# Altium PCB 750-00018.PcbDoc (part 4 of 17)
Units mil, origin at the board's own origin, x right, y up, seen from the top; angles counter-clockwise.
Board outline 7086.64 x 6299.21 mil, 8 copper layers (Top Layer, L2, L3, L4, L5, L6, L7, Bottom Layer), stack 60.6 mil thick; 1356 components, 1054 nets, 4851 pads, 4296 vias.
Unrouted connection lines stored in the file: 12.
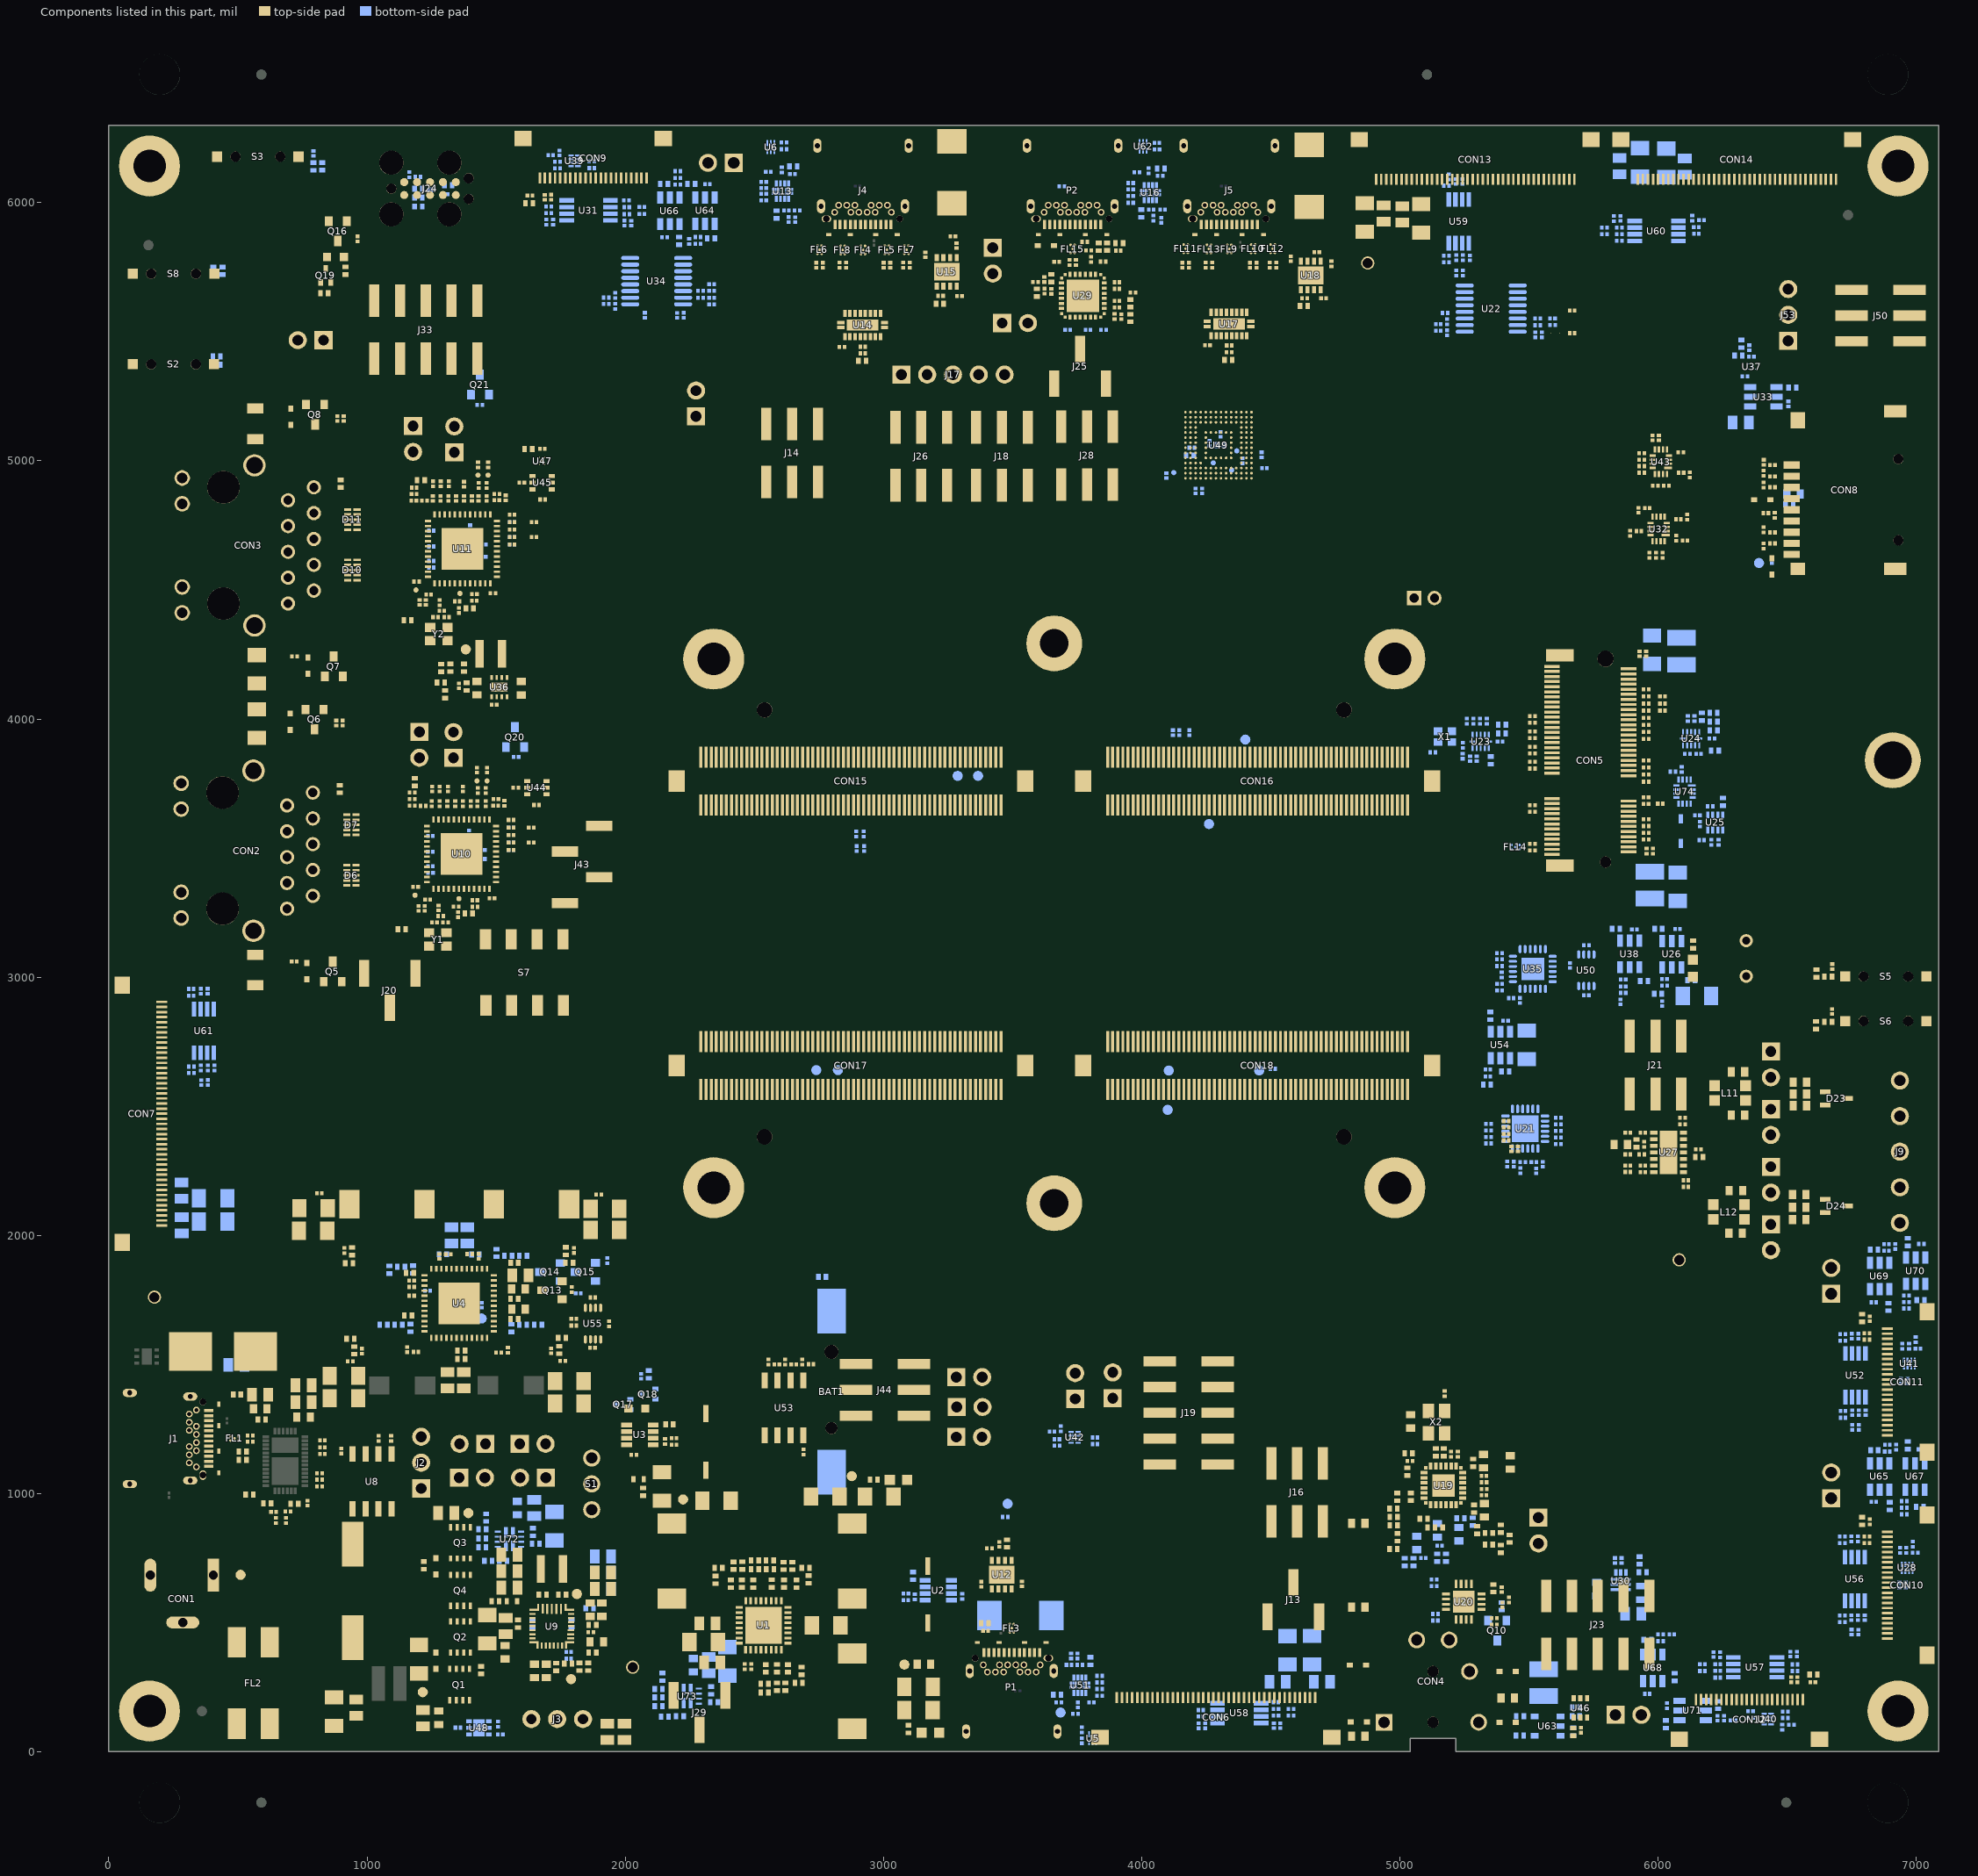
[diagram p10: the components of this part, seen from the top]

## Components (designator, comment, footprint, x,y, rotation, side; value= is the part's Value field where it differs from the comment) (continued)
U9 "TI, BQ25792RQM#" "VQFN29, 4x4, Pitch 0.45 & 0.4mm, Height 1mm" 1715.57,486.56 r0 top value=BQ25792RQM#
U10 "TI, DP83867IRRGZ" "QFN48, 7x7, Pitch 0.5mm, Height 1.0mm" 1365.54,3476.67 r0 top value=DP83867IRRGZ
U11 "TI, DP83867IRRGZ" "QFN48, 7x7, Pitch 0.5mm, Height 1.0mm" 1369.48,4658.99 r0 top value=DP83867IRRGZ
U12 "TI, TPS2557DRBT" "VSON8, 3mm x 3mm, Height 1.0mm, SMD" 3458.2,686 r270 top value=TPS2557DRBT
U13 "TI, TUSB321RWBR" "X2QFN12, 1.6mm x 1.6mm, Pitch 0.4mm, Height 0.4mm, SMD" 2608.95,6043.99 r180 bottom value=TUSB321RWBR
U14 "TI, HD3SS3212IRKST" "VQFN20, 2.5x4.5, Pitch 0.5mm, Height 1.0mm, SMD" 2919.66,5525.87 r90 top value=HD3SS3212IRKST
U15 "TI, TPS2557DRBT" "VSON8, 3mm x 3mm, Height 1.0mm, SMD" 3244.75,5732.09 r90 top value=TPS2557DRBT
U16 "TI, TUSB321RWBR" "X2QFN12, 1.6mm x 1.6mm, Pitch 0.4mm, Height 0.4mm, SMD" 4033.67,6038.46 r180 bottom value=TUSB321RWBR
U17 "TI, HD3SS3212IRKST" "VQFN20, 2.5x4.5, Pitch 0.5mm, Height 1.0mm, SMD" 4338.14,5529.98 r90 top value=HD3SS3212IRKST
U18 "TI, TPS2557DRBT" "VSON8, 3mm x 3mm, Height 1.0mm, SMD" 4654.57,5718.14 r90 top value=TPS2557DRBT
U19 "TI, TAC5112IRGER" "VQFN24, 4x4, Pitch 0.5mm, Height 1.0mm, SMD with Anchor Pads" 5168.69,1031.74 r180 top value=TAC5112IRGER
U20 "TI, TS3A227ERVAR" "QFN16, 3.5x3.5, Pitch 0.5mm, Height 1.0mm" 5247,581.34 r180 top value=TS3A227ERVAR
U21 "Microchip, MCP23018-E/MJ" "VQFN24, 4x4, Pitch 0.5mm, Height 0.9mm" 5485.26,2413.17 r270 bottom value=MCP23018-E/MJ
U22 "TI, TCA9546APWR" "TSSOP16, 16-Leads, Body 5.0mm x 4.4mm, Height 1.2mm, Pitch 0.65mm" 5353.7,5589.13 r0 bottom value=TCA9546APWR
U23 "TI, LSF0204RUTR" "TI, RUT12" 5312.93,3912.95 r90 bottom value=LSF0204RUTR
U24 "TI, LSF0204RUTR" "TI, RUT12" 6127.81,3924.27 r90 bottom value=LSF0204RUTR
U25 "TI, TPS2116DRLR" "SOT8, 2.1x1.6mm, Height 0.6mm" 6221.4,3599.27 r90 bottom value=TPS2116DRLR
U26 "TI, TPS22918DBVR" "SOT23_6, Height 1.45mm" 6053.01,3089.32 r90 bottom value=TPS22918DBVR
U27 "TI, TCAN1046AVDMTRQ1" "SON14, 4.5mm x 3mm x 1mm, SMD" 6040.4,2320.97 r0 top value=TCAN1046AVDMTRQ1
U28 "TI, LSF0102DQER" "XFDFN8, 1.4x1.0, 0.4mm" 6964.7,712.89 r90 bottom value=LSF0102DQER
U29 "FTDI, FT232RNQ" "QFN32, 5x5, Pitch 0.5mm, Height 0.9mm" 3771.98,5639.24 r180 top value=FT232RNQ
U30 "TI, TPS62902RPJR" "VQFN-HR(9), 1.5mm x 2.0mm, Pitch 0.5mm, Height 1mm, SMD" 5855.43,658.16 r180 bottom value=TPS62902RPJR
U31 "TI, TCA9617BDGKR" "TSSOP8, 4.9x3, Pitch 0.65mm, Height 1.1mm" 1857.97,5969.85 r0 bottom value=TCA9617BDGKR
U32 "TI, TMUX1574RSVR" "UQFN16, 2.6x1.8, Pitch 0.4mm, Height 0.5mm" 6001.69,4735.84 r180 top value=TMUX1574RSVR
U33 "TI, TPS22918DBVR" "SOT23_6, Height 1.45mm" 6407.31,5247.2 r0 bottom value=TPS22918DBVR
U34 "TI, TCA9546APWR" "TSSOP16, 16-Leads, Body 5.0mm x 4.4mm, Height 1.2mm, Pitch 0.65mm" 2121.74,5695.52 r0 bottom value=TCA9546APWR
U35 "TI, TCAL9539RTWR" "QFN24, 4x4, Pitch 0.5mm, Height 0.8mm" 5514.39,3031.87 r270 bottom value=TCAL9539RTWR
U36 "TI, TLV62065DSGR" DSG0008A 1511.91,4123.41 r270 top value=TLV62065DSGR
U37 "TI, SN74LVC1G08DPWR" "TI, SN74LVC1G08DPWR" 6362.83,5365.12 r180 bottom value=SN74LVC1G08DPWR
U38 "TI, TPS22918DBVR" "SOT23_6, Height 1.45mm" 5889.82,3089.76 r90 bottom value=TPS22918DBVR
U39 "TI, LSF0102DQER" "XFDFN8, 1.4x1.0, 0.4mm" 1803.57,6161.77 r180 bottom value=LSF0102DQER
U40 "TI, LSF0102DQER" "XFDFN8, 1.4x1.0, 0.4mm" 6423.85,126.58 r0 bottom value=LSF0102DQER
U41 "TI, LSF0102DQER" "XFDFN8, 1.4x1.0, 0.4mm" 6973.27,1503.66 r90 bottom value=LSF0102DQER
U42 "TI, LSF0102DQER" "XFDFN8, 1.4x1.0, 0.4mm" 3740.28,1217.63 r180 bottom locked value=LSF0102DQER
U43 "TI, TMUX1574RSVR" "UQFN16, 2.6x1.8, Pitch 0.4mm, Height 0.5mm" 6010.92,4996.31 r180 top value=TMUX1574RSVR
U44 "TI, SN74LVC1G11DCKR" SC70-6 1657.18,3734.43 r90 top value=SN74LVC1G11DCKR
U45 "TI, SN74LVC1G11DCKR" SC70-6 1678.63,4915.1 r90 top value=SN74LVC1G11DCKR
U46 "TI, SN74LVC1G11DCKR" SC70-6 5698.88,169.53 r180 top value=SN74LVC1G11DCKR
U47 "TI, SN74LVC1G08DPWR" "TI, SN74LVC1G08DPWR" 1678.3,4999.19 r90 top value=SN74LVC1G08DPWR
U48 "TI, TPS22810DRVR" "WSON6, 2x2, SMD" 1432.99,92.39 r180 bottom locked value=TPS22810DRVR
U49 "Western Digital, SDINBDG4-8G-XI2" "BGA153, 13mmx11.5mm, Height 0.8mm" 4297.3,5060.41 r90 top locked value=SDINBDG4-8G-XI2
U50 "TI, TXS0102DCU" VFSOP8_2x2.3 5721.89,3026.93 r0 bottom value=TXS0102DCU
U51 "TI, TUSB321RWBR" "X2QFN12, 1.6mm x 1.6mm, Pitch 0.4mm, Height 0.4mm, SMD" 3760.54,257.96 r0 bottom value=TUSB321RWBR
U52 "TI, TCA9617BDGKR" "TSSOP8, 4.9x3, Pitch 0.65mm, Height 1.1mm" 6763.89,1458.07 r270 bottom value=TCA9617BDGKR
U53 "Giantec, GT24C256C-2GLI-TR" SOIC-8 2614.85,1332.2 r270 top value=GT24C256C-2GLI-TR
U54 "TI, TPS22918DBVR" "SOT23_6, Height 1.45mm" 5388.7,2737.62 r90 bottom value=TPS22918DBVR
U55 "TI, TXS0102DCU" VFSOP8_2x2.3 1875.05,1658.33 r0 top value=TXS0102DCU
U56 "TI, TCA9617BDGKR" "TSSOP8, 4.9x3, Pitch 0.65mm, Height 1.1mm" 6761.86,669.56 r270 bottom value=TCA9617BDGKR
U57 "TI, TCA9617BDGKR" "TSSOP8, 4.9x3, Pitch 0.65mm, Height 1.1mm" 6375.33,326.98 r180 bottom value=TCA9617BDGKR
U58 "TI, TCA9617BDGKR" "TSSOP8, 4.9x3, Pitch 0.65mm, Height 1.1mm" 4378.07,149.7 r0 bottom value=TCA9617BDGKR
U59 "TI, TCA9617BDGKR" "TSSOP8, 4.9x3, Pitch 0.65mm, Height 1.1mm" 5228.11,5927.7 r270 bottom value=TCA9617BDGKR
U60 "TI, TCA9617BDGKR" "TSSOP8, 4.9x3, Pitch 0.65mm, Height 1.1mm" 5993.7,5890.15 r180 bottom value=TCA9617BDGKR
U61 "TI, TCA9617BDGKR" "TSSOP8, 4.9x3, Pitch 0.65mm, Height 1.1mm" 368.11,2791.79 r270 bottom value=TCA9617BDGKR
U62 "TI, SN74AUP1G125DSFR" "X2SON, Height 0.4mm" 4005.51,6217.85 r90 bottom value=SN74AUP1G125DSFR
U63 "TI, TPS73433TDDCRQ1" "TI, SOT23-5 (DDC0005A)" 5571.85,99.33 r180 bottom value=TPS73433TDDCRQ1
U64 "TI, TPS22918DBVR" "SOT23_6, Height 1.45mm" 2308.71,5968.85 r90 bottom value=TPS22918DBVR
U65 "TI, TPS22918DBVR" "SOT23_6, Height 1.45mm" 6857.25,1065.88 r270 bottom value=TPS22918DBVR
U66 "TI, TPS22918DBVR" "SOT23_6, Height 1.45mm" 2172.47,5968.09 r270 bottom value=TPS22918DBVR
U67 "TI, TPS22918DBVR" "SOT23_6, Height 1.45mm" 6994.75,1066.05 r90 bottom value=TPS22918DBVR
U68 "TI, TPS22918DBVR" "SOT23_6, Height 1.45mm" 5979.72,325.15 r270 bottom value=TPS22918DBVR
U69 "TI, TPS22918DBVR" "SOT23_6, Height 1.45mm" 6857.25,1842.31 r270 bottom value=TPS22918DBVR
U70 "TI, TPS22918DBVR" "SOT23_6, Height 1.45mm" 6997.18,1862.95 r90 bottom value=TPS22918DBVR
U71 "TI, TPS22918DBVR" "SOT23_6, Height 1.45mm" 6133.56,160.3 r180 bottom value=TPS22918DBVR
U72 "TI, TPS2121RUXR" "VQFN-HR(12), 2.5mm x 2.0mm, Pitch 0.5mm & 0.7mm, Height 1mm" 1551.07,823.4 r90 bottom value=TPS2121RUXR
U73 "TI, TPS2121RUXR" "VQFN-HR(12), 2.5mm x 2.0mm, Pitch 0.5mm & 0.7mm, Height 1mm" 2240.12,215.44 r90 bottom value=TPS2121RUXR
U74 "ON Semi, FSA2466UMX" "UQFN16, 2.6x1.8, Pitch 0.4mm, Height 0.5mm" 6102.72,3718.97 r180 bottom value=FSA2466UMX
X1 "Siward, OSCA23300-SCO-G646" "Oscillator, 4 pin, 1.6mm x 2.0mm" 5174.64,3931.85 r0 bottom value="32.768 kHz"
X2 "Siward, OSC813250-SCO-B192" "Oscillator, 4 pin, 3.2mm x 2.5mm" 5141.75,1276.89 r270 top value=12.288MHz
Y1 "Siward, XTL581200-P120-165" "Crystal, 4 pin, 2.5mm x 2.0mm" 1273.91,3146.57 r0 top value=25MHz
Y2 "Siward, XTL581200-P120-165" "Crystal, 4 pin, 2.5mm x 2.0mm" 1277.85,4328.89 r0 top value=25MHz

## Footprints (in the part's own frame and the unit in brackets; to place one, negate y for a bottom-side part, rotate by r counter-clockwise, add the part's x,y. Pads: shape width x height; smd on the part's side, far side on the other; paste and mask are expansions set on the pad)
"2P0MM-1X2, male" [mil] "Pin Header, TH, 1X2P, Pitch 2.0mm, 180 Degree(38/20/30)"
  rect 55x55 hole 35 mask+2: 1(-39.37,0)
  round 55 hole 35 mask+2: 2(39.37,0)
  silkscreen extent -87,-47 87,47, body extent -79,-39 79,39, height 228
"2P54MM-1X2 with frction Lock" [mil] "Vertical Header, DIP, 1X2P with friction Lock, Pitch 2.54mm"
  rect 70x70 / inner round 70 / far side rect 70x70 hole 44.88: 1(-50,0)
  round 70 hole 44.88: 2(50,0)
  silkscreen extent -103,-135 105,125, body extent -97,-130 97,120, height 416
"2P54MM-1X2, male" [mil] "Pin Header, DIP, 1X2P, Pitch 2.54mm, 180 Degree(60/25/30)"
  rect 70x70 / inner round 70 / far side rect 70x70 hole 42: 1(-50,0)
  round 70 hole 42: 2(50,0)
  silkscreen extent -103,-54 105,54, body extent -100,-49 100,49, height 335
"2P54MM-1X3, Male" [mil] "Pin Header, DIP, 1X3P, Pitch 2.54mm, 180 Degree(60/25/30)"
  rect 70x70 / inner round 70 / far side rect 70x70 hole 42: 1(-100,0)
  round 70 hole 42: 2(0,0) 3(100,0)
  silkscreen extent -153,-54 155,54, body extent -148,-49 152,49, height 335
"2P54MM-1X3, male" [mm] "Pin Header, SMT, male, 1X3, Pitch 2.54mm, PHY 0.64mm, 180 (60/33)"
  rect 1x2.6 smd: 1(-2.54,-1.7) 2(0,1.7) 3(2.54,-1.7)
  silkscreen extent -3.81,-3.45 3.81,3.35, body extent -3.81,-2.5 3.81,2.5, height 9.82
"2P54MM-1X4, male" [mm] "Pin Header, SMT, male, 1X4, Pitch 2.54mm, PHY 0.64mm, 180 (60/33)"
  rect 1x2.6 smd: 1(-3.81,1.7) 2(-1.27,-1.7) 3(1.27,1.7) 4(3.81,-1.7)
  silkscreen extent -5.08,-3.45 5.08,3.35, body extent -5.08,-2.5 5.08,2.5, height 9.82
"2P54MM-2X3 Male" [mm] "Pin Header, SMT, 2X3P, Pitch 2.54mm, 180 Degree(60/33)"
  rect 1x3.2 smd: 1(-2.54,-2.85) 2(-2.54,2.85) 3(0,-2.85) 4(0,2.85) 5(2.54,-2.85) 6(2.54,2.85)
  silkscreen extent -3.81,-2.54 3.81,2.54, body extent -3.81,-3.75 3.81,3.75, height 9.7
"2P54MM-2X5 Male" [mm] "Pin Header, SMT, 2X5P, Pitch 2.54mm, 180 Degree(60/33)"
  rect 1x3.2 smd: 1(-5.08,-2.85) 2(-5.08,2.85) 3(-2.54,-2.85) 4(-2.54,2.85) 5(0,-2.85) 6(0,2.85) 7(2.54,-2.85) 8(2.54,2.85) 9(5.08,-2.85) 10(5.08,2.85)
  silkscreen extent -6.35,-2.54 6.35,2.54, body extent -6.25,-3.75 6.35,3.75, height 9.7
"Adam Tech, BH-44F-5" [mm] "BATTERY HOLDER, SMT, COIN CELL, CR1220"
  rect 4.4x2.8 smd paste-4 mask+0.102: 1(-7.925,0) 2(7.925,0)
  round 1.4 hole 1.4 unplated mask+0.102: 3(-3.9,0)
  round 1.2 hole 1.2 unplated mask+0.102: 4(3.6,0)
  silkscreen extent -8.81,-9 8.81,9, body extent -9.8,-7.45 9.45,7.45, height 4.1
"AUDIO JACK, 3.5mm" [mm] "AUDIO JACK, TH, body 14 x 10.2 x 5mm, Mating plug 3.5mm"
  rect 1.65x1.65 hole 1.1: 1(-4.05,4.8)
  round 1.65 hole 1.1: 2(0.95,-3.6) 3(4.05,1.6) 4(-4.05,-4.5) 5(4.05,-1.6)
  round 1.1 hole 1.1 unplated: 6(-4.05,0) 7(0.95,0)
  silkscreen extent -9.95,-4.3 4.05,4.7, body extent -9.5,-5.3 4.5,4.9, height 5.23
"BGA153, 13mmx11.5mm, Height 0.8mm" [mil] "BGA153, 153-Leads, Body 13x11.5mm, Height 0.8mm, Pitch 0.5mm"
  round 10 smd mask+2: A1(-127.95,127.95) A2(-108.27,127.95) A3(-88.58,127.95) A4(-68.9,127.95) A5(-49.21,127.95) A6(-29.53,127.95) A7(-9.84,127.95) A8(9.84,127.95) A9(29.53,127.95) A10(49.21,127.95) A11(68.9,127.95) A12(88.58,127.95) A13(108.27,127.95) A14(127.95,127.95) B1(-127.95,108.27) B2(-108.27,108.27) B3(-88.58,108.27) B4(-68.9,108.27) B5(-49.21,108.27) B6(-29.53,108.27) B7(-9.84,108.27) B8(9.84,108.27) B9(29.53,108.27) B10(49.21,108.27) B11(68.9,108.27) B12(88.58,108.27) B13(108.27,108.27) B14(127.95,108.27) C1(-127.95,88.58) C2(-108.27,88.58) C3(-88.58,88.58) C4(-68.9,88.58) C5(-49.21,88.58) C6(-29.53,88.58) C7(-9.84,88.58) C8(9.84,88.58) C9(29.53,88.58) C10(49.21,88.58) C11(68.9,88.58) C12(88.58,88.58) C13(108.27,88.58) C14(127.95,88.58) D1(-127.95,68.9) D2(-108.27,68.9) D3(-88.58,68.9) D4(-68.9,68.9) D12(88.58,68.9) D13(108.27,68.9) D14(127.95,68.9) E1(-127.95,49.21) E2(-108.27,49.21) E3(-88.58,49.21) E5(-49.21,49.21) E6(-29.53,49.21) E7(-9.84,49.21) E8(9.84,49.21) E9(29.53,49.21) E10(49.21,49.21) E12(88.58,49.21) E13(108.27,49.21) E14(127.95,49.21) F1(-127.95,29.53) F2(-108.27,29.53) F3(-88.58,29.53) F5(-49.21,29.53) F10(49.21,29.53) F12(88.58,29.53) F13(108.27,29.53) F14(127.95,29.53) G1(-127.95,9.84) G2(-108.27,9.84) G3(-88.58,9.84) G5(-49.21,9.84) G10(49.21,9.84) G12(88.58,9.84) G13(108.27,9.84) G14(127.95,9.84) H1(-127.95,-9.84) H2(-108.27,-9.84) H3(-88.58,-9.84) H5(-49.21,-9.84) H10(49.21,-9.84) H12(88.58,-9.84) H13(108.27,-9.84) H14(127.95,-9.84) J1(-127.95,-29.53) J2(-108.27,-29.53) J3(-88.58,-29.53) J5(-49.21,-29.53) J10(49.21,-29.53) J12(88.58,-29.53) J13(108.27,-29.53) J14(127.95,-29.53) K1(-127.95,-49.21) K2(-108.27,-49.21) K3(-88.58,-49.21) K5(-49.21,-49.21) K6(-29.53,-49.21) K7(-9.84,-49.21) K8(9.84,-49.21) K9(29.53,-49.21) K10(49.21,-49.21) K12(88.58,-49.21) K13(108.27,-49.21) K14(127.95,-49.21) L1(-127.95,-68.9) L2(-108.27,-68.9) L3(-88.58,-68.9) L12(88.58,-68.9) L13(108.27,-68.9) L14(127.95,-68.9) M1(-127.95,-88.58) M2(-108.27,-88.58) M3(-88.58,-88.58) M4(-68.9,-88.58) M5(-49.21,-88.58) M6(-29.53,-88.58) M7(-9.84,-88.58) M8(9.84,-88.58) M9(29.53,-88.58) M10(49.21,-88.58) M11(68.9,-88.58) M12(88.58,-88.58) M13(108.27,-88.58) M14(127.95,-88.58) N1(-127.95,-108.27) N2(-108.27,-108.27) N3(-88.58,-108.27) N4(-68.9,-108.27) N5(-49.21,-108.27) N6(-29.53,-108.27) N7(-9.84,-108.27) N8(9.84,-108.27) N9(29.53,-108.27) N10(49.21,-108.27) N11(68.9,-108.27) N12(88.58,-108.27) N13(108.27,-108.27) N14(127.95,-108.27) P1(-127.95,-127.95) P2(-108.27,-127.95) P3(-88.58,-127.95) P4(-68.9,-127.95) P5(-49.21,-127.95) P6(-29.53,-127.95) P7(-9.84,-127.95) P8(9.84,-127.95) P9(29.53,-127.95) P10(49.21,-127.95) P11(68.9,-127.95) P12(88.58,-127.95) P13(108.27,-127.95) P14(127.95,-127.95)
  silkscreen extent -230,-260 230,260, body extent -226,-256 226,256, height 31
"CAP, 0805, 1.45mm, HD" [mm] "CAP, 0805, 1.45mm, HD"
  rect 0.95x1.35 smd: 1(-0.8,0) 2(0.8,0)
  silkscreen extent -0.05,-0.58 0.05,0.58, body extent -1.1,-0.72 1.1,0.73, height 1.45
"CAP, 1206, 1.8mm, HD" [mm] "SMD, 1206, Body 3.5x1.8mm, IPC Medium Density"
  rect 1.4x1.8 smd: 1(-1.4,0) 2(1.4,0)
  silkscreen extent -0.3,-0.8 0.3,0.8, body extent -1.6,-0.9 1.6,0.9, height 1.6
"CAP, 1210, 2.8mm" [mm] "Chip Capacitor, 1210, Body 3.20x2.50mm, x2.8mm Height Medium Density"
  rect 1.55x2.8 smd: 1(-1.325,0) 2(1.325,0)
  silkscreen extent -2.35,-1.65 2.35,1.65, body extent -1.75,-1.4 1.75,1.4, height 2.7
"CAP, 7343, Polarized, 2.8mm" [mm] "CAP,Body 7.3x4.3, Height 2.80mm, Polarized"
  rect 2.4x2.9 smd mask+0.051: 1(-3.05,0) 2(3.05,0)
  silkscreen extent -3.65,-2.15 3.65,2.15, body extent -3.85,-2.15 3.85,2.15, height 2.93
"Cap, C0201, Height 0.3mm" [mil] "Capacitor, C0201, Body 0.6 x 0.3mm, Height 0.3mm"
  rect 13.84x15.81 smd paste-2.01 mask-2.01: 1(-9.84,0)
  rect 13.86x15.83 smd paste-2.01 mask-2.01: 2(9.85,0)
  silkscreen extent -20,-11 20,11, body extent -12,-6 12,6, height 12
"CAP, CAPAE, 8mm Dia." [mm] "Aluminum Electrolytic Capacitor, TH, Body 8X3.5x11.5mm"
  round 1.3 hole 0.8 mask+0.051: 1(-1.75,0) 2(1.75,0)
  silkscreen extent -3.97,-4.03 4.03,4, body extent -4,-4 4.01,4, height 11.51
"CAP, CAPAE, 10.5mm Dia." [mm] "Aluminum Electrolytic Capacitor, Body 10.30x10.30x10.50mm, IPC Medium Density"
  rect 4.4x2.1 smd: 1(-4.6,0) 2(4.6,0)
  silkscreen extent -5.25,-5.25 5.25,5.25, body extent -6.1,-5.23 6.1,5.27, height 10.56
"Chip, 0603, RF" [mil] "Chip, 0603 RF, Body 1.6x0.8mm, Height 0.8mm, NON IPC RF"
  rect 28x36 smd paste-2 mask-2: 1(-26,0) 2(26,0)
  silkscreen extent -43,-21 43,21, body extent -32,-16 31,16, height 31
"Chip. 0402, RF" [mm] "Chip, 0402 RF, Body 1.0x0.5mm, Height 0.5mm, NON IPC RF"
  rect 0.452x0.602 smd paste-0.051 mask-0.051: 1(-0.375,0) 2(0.375,0)
  silkscreen extent -0.67,-0.37 0.67,0.37, body extent -0.5,-0.25 0.5,0.25, height 0.5
"Choke , 3225, Height 2.4mm" [mm] "Choke Coil, 4-Leads, Body 3.2x2.5mm, Height 2.4mm"
  rect 1.05x1.05 smd mask+0.051: 1(-0.725,1.525) 2(-0.725,-1.525) 3(0.725,-1.525) 4(0.725,1.525)
  silkscreen extent -1.36,-2.19 1.36,2.18, body extent -1.26,-1.61 1.26,1.61, height 2.4
"Crystal, 4 pin, 2.5mm x 2.0mm" [mm] "Crystal, 4 pin, Body 2.5mm x 2.0mm, Height 0.65mm"
  rect 1x0.9 smd mask+0.051: 1(-0.85,-0.65) 2(0.85,-0.65) 3(0.85,0.65) 4(-0.85,0.65)
  silkscreen extent -1.5,-1.24 1.5,1.24, body extent -1.25,-1 1.25,1, height 0.65
DFN10L [mil] "DFN10L, 10-Leads, 2.5mm x 1mm, Height 0.5mm"
  rect 28x10 smd mask+2: 1(-18,39.37) 2(-18,19.69) 3(-18,0) 4(-18,-19.69) 5(-18,-39.37) 6(18,-39.37) 7(18,-19.69) 8(18,0) 9(18,19.69) 10(18,39.37)
  silkscreen extent -29,-58 29,58, body extent -20,-49 20,49, height 20
"Diptronics, DJR-04-T-V" [mm] "Switch Slide, SMT, SPST, 11.10mm x 7.87mm, Height 3.77mm"
  rect 2x1.1 smd mask+0.051: 1(-3.25,3.789) 2(-3.25,1.249) 3(-3.25,-1.291) 4(-3.25,-3.831) 5(3.25,-3.789) 6(3.25,-1.249) 7(3.25,1.291) 8(3.25,3.831)
  silkscreen extent -4.44,-5.55 4.44,5.55, body extent -3.94,-5.55 3.93,5.55, height 3.93
DSG0008A [mm] "WSON, 8-Leads, Body 2.1x2.1mm, Pitch 0.5mm, Height 0.8mm"
  rect 0.5x0.25 smd mask+0.05: 1(-0.95,0.75) 2(-0.95,0.25) 3(-0.95,-0.25) 4(-0.95,-0.75) 5(0.95,-0.75) 6(0.95,-0.25) 7(0.95,0.25) 8(0.95,0.75)
  rect 0.9x1.6 smd paste-2539.97 mask+0.05: 9(0,0)
  silkscreen extent -1.05,-1.2 1.05,1.2, body extent -1,-1 1,1, height 0.78
"E-Switch, 500ASSP1M2QE" [mm] "Switch Slide, DIP90, SPDT, 10.16mm x 5.08mm, Height 13.32mm"
  round 1.69 hole 1.09 mask+0.051: 1(-2.54,0) 2(0,0) 3(2.54,0)
  silkscreen extent -5.08,-2.54 5.08,2.54, body extent -5.08,-2.54 5.08,2.54, height 13.11
"Everlight, 0402, 0.25mm Height" [mm]
  rect 0.4x0.6 smd mask+0.051: 1(-0.5,0) 2(0.5,0)
  silkscreen extent -0.82,-0.42 1.61,1.26, body extent -0.5,-0.25 0.5,0.25, height 0.16
"EW-Switch, BTS-1101NE-2-BB-RP-K" [mm] "Switch tact, SMT, SPST, 8.6mm x 3.5mm, Height 4.3mm"
  rect 1x1 smd mask+0.051: 1(-4,0) 2(4,0)
  round 1 hole 1 unplated mask+0.051: 3(-2.2,0) 4(2.2,0)
  silkscreen extent -4.62,-1.75 4.62,1.75, body extent -4.3,-1.75 4.3,1.75, height 4.3
"FB, FB0402, RF" [mm] "Ferrite Bead, FB0402, Body 1.0 x 0.5mm, Height 0.55mm"
  rect 0.452x0.602 smd paste-0.051 mask-0.051: 1(-0.375,0) 2(0.375,0)
  silkscreen extent -0.67,-0.37 0.67,0.37, body extent -0.52,-0.27 0.53,0.28, height 0.55
"FB, FB0603, RF" [mil] "Ferrite Bead, FB0603, Body 1.6 x 0.8mm, Height 0.8mm"
  rect 28x36 smd paste-2 mask-2: 1(-26,0) 2(26,0)
  silkscreen extent -43,-21 43,21, body extent -31,-16 31,16, height 31
"Fixed Terminal Blocks-1X5" [mil] "Fixed Terminal Blocks, DIP, 1X5P, Pitch 3.5mm, 90 Degree"
  round 70 hole 43.31: 1(-275.59,0) 2(-137.8,0) 3(0,0) 4(137.8,0) 5(275.59,0)
  silkscreen extent -364,-134 364,134, body extent -364,-134 364,134, height 331
"IND, 9.2x7.5mm Height 2.5mm" [mm] "Power Inductor, 2-Leads, Body 9.2x7.5mm, Height 2.5mm"
  rect 2x2.8 smd mask+0.051: 1(-3.7,0) 2(3.7,0)
  silkscreen extent -4.6,-3.75 4.6,3.75, body extent -4.6,-3.75 4.6,3.75, height 2.5
"IND, 2016, Height 1.0mm" [mm] "Power Inductor, 2-Leads, Body 2.0 x 1.6mm, Height 1.0mm"
  rect 0.65x1.6 smd mask+0.051: 1(-0.675,0) 2(0.675,0)
  silkscreen extent -0.92,-1.03 0.92,1.02, body extent -1,-0.8 1,0.8, height 1.01
"IND, 3030, Height 1.2mm" [mm] "Power Inductor, 2-Leads, Body 3.0x3.0mm, Height 1.2mm"
  rect 0.8x2.7 smd mask+0.051: 1(-1.1,0) 2(1.1,0)
  silkscreen extent -1.5,-1.5 1.5,1.5, body extent -1.5,-1.5 1.5,1.5, height 1.2
"JAE, SM3ZS067U410AER1000" [mm] "JAE, M.2 Key-E, 67 pins, Pitch 0.5mm, Height 4.1mm"
  rect 0.3x1.55 smd mask+0.051: 1(8.361,-2.886) 2(8.111,4.664) 3(7.861,-2.886) 4(7.611,4.664) 5(7.361,-2.886) 6(7.111,4.664) 7(6.861,-2.886) 8(6.611,4.664) 9(6.361,-2.886) 10(6.111,4.664) 11(5.861,-2.886) 12(5.611,4.664) 13(5.361,-2.886) 14(5.111,4.664) 15(4.861,-2.886) 16(4.611,4.664) 17(4.361,-2.886) 18(4.111,4.664) 19(3.861,-2.886) 20(3.611,4.664) 21(3.361,-2.886) 22(3.111,4.664) 23(2.861,-2.886) 32(0.635,4.664) 33(0.361,-2.886) 34(0.111,4.664) 35(-0.139,-2.886) 36(-0.389,4.664) 37(-0.639,-2.886) 38(-0.889,4.664) 39(-1.139,-2.886) 40(-1.389,4.664) 41(-1.639,-2.886) 42(-1.889,4.664) 43(-2.139,-2.886) 44(-2.389,4.664) 45(-2.639,-2.886) 46(-2.889,4.664) 47(-3.139,-2.886) 48(-3.389,4.664) 49(-3.639,-2.886) 50(-3.889,4.664) 51(-4.139,-2.886) 52(-4.389,4.664) 53(-4.639,-2.886) 54(-4.889,4.664) 55(-5.139,-2.886) 56(-5.389,4.664) 57(-5.639,-2.886) 58(-5.889,4.664) 59(-6.139,-2.886) 60(-6.389,4.664) 61(-6.639,-2.886) 62(-6.889,4.664) 63(-7.139,-2.886) 64(-7.389,4.664) 65(-7.639,-2.886) 66(-7.889,4.664) 67(-8.139,-2.886) 68(-8.389,4.664) 69(-8.639,-2.886) 70(-8.889,4.664) 71(-9.139,-2.886) 72(-9.389,4.664) 73(-9.639,-2.886) 74(-9.889,4.664) 75(-10.139,-2.886)
  rect 1.2x2.75 smd mask+0.051: 76(9.461,-2.111) 77(-11.239,-2.111)
  round 1.1 hole 1.1 unplated: 78(9.111,2.389)
  round 1.6 hole 1.6 unplated: 79(-10.889,2.389)
  silkscreen extent -11.89,-0.36 10.11,5.14, body extent -11.85,-3.46 10.05,5.24, height 4.07
"Kingbright, LED0603, Green" [mm] "LED, SMT, Body 1.6 x 0.8 mm, 0.25mm Thickness"
  rect 0.8x0.8 smd paste+0: 1(0.825,0) 2(-0.825,0)
  body extent -0.8,-0.4 0.8,0.4, height 0.25
"Kingbright, LED0603, Orange" [mm] "LED, SMT, Body 1.6 x 0.8 mm, 0.25mm Thickness"
  rect 1x1 smd paste+0 mask+0: 1(0.85,0) 2(-0.85,0)
  body extent -0.8,-0.4 0.8,0.4, height 0.25
"Kingconn, 7MSDP-BA-1011-D" [mm] "CON, Micro SD Push Type"
  rect 0.7x1.6 smd mask+0.051: 1(2.45,5.25) 2(1.35,5.25) 3(0.25,5.25) 4(-0.85,5.25) 5(-1.95,5.25) 6(-3.05,5.25) 7(-4.15,5.25) 8(-5.25,5.25) 9(-6.35,5.25)
  rect 1.6x1.4 smd mask+0.051: 10(6.85,4.65)
  rect 1.2x2.2 smd mask+0.051: 11(7.75,-4.95) 13(-7.75,-4.95)
  rect 1.2x1.4 smd mask+0.051: 12(-7.75,4.65)
  round 1 hole 1 unplated mask+0.051: 14(-4.95,-5.25) 15(3.05,-5.25)
  silkscreen extent -8.46,-9.22 8.48,6.2, body extent -8.05,-9.22 8.05,5.98, height 1.9
"Kingconn, 7RJ45-F0-0332" [mm] "CON, TH, 1x1 Port, RJ-45 with LED"
  round 1.4 hole 0.89: 1(-5.715,6.475) 2(-4.445,3.935) 3(-3.175,6.475) 4(-1.905,3.935) 5(-0.635,6.475) 6(0.635,3.935) 7(1.905,6.475) 8(3.175,3.935) 9(4.445,6.475) 10(5.715,3.935)
  round 1.53 hole 1.02: 11(-6.63,-6.475) 12(-4.09,-6.475) 13(4.09,-6.475) 14(6.63,-6.475)
  round 2.2 hole 1.63: 15(-7.875,0.635) 16(7.875,0.635)
  round 3.2 hole 3.2 unplated: 17(-5.715,-2.415) 18(5.715,-2.415)
  silkscreen extent -9.53,-13.17 9.17,7.95, body extent -9.53,-13.17 9.17,7.94, height 14.81
"Kingconn, 7USB31-F0-0029" [mm] "USB, 24P, C TYPE"
  oval 0.8x1.4 hole 0.5 slot 1.1 at 90 deg mask+0.051: 1(-4.13,1.575) 2(4.13,1.575) 3(-4.49,-4.375) 4(4.49,-4.375)
  rect 0.5x0.3 smd mask+0.051: 5(-3.375,4.375) 6(-1.25,4.375) 7(1.25,4.375) 8(3.375,4.375)
  round 0.65 hole 0.65 unplated mask+0.051: 9(-3.6,2.825)
  oval 0.95x0.65 hole 0.65 slot 0.95 at 0 deg unplated mask+0.051: 10(3.6,2.825)
  rect 0.3x0.9 smd mask+0.051: A1(-2.75,3.385) A2(-2.25,3.385) A3(-1.75,3.385) A4(-1.25,3.385) A5(-0.75,3.385) A6(-0.25,3.385) A7(0.25,3.385) A8(0.75,3.385) A9(1.25,3.385) A10(1.75,3.385) A11(2.25,3.385) A12(2.75,3.385)
  round 0.66 hole 0.4 mask+0.051: B1(2.8,2.175) B2(2.4,1.475) B3(1.6,1.475) B4(1.2,2.175) B5(0.8,1.475) B6(0.4,2.175) B7(-0.4,2.175) B8(-0.8,1.475) B9(-1.2,2.175) B10(-1.6,1.475) B11(-2.4,1.475) B12(-2.8,2.175)
  silkscreen extent -4.59,-6.38 4.59,4.47, body extent -4.62,-6.38 4.62,4.47, height 3.39
"Kyocera, 145046120640868+" [mm] "Board to Board & Mezzanine Connectors, Plug, 0.5mm Pitch, 120 Position, 4.0mm Height"
  rect 2.1x0.3 smd mask+0.051: 1(2.35,14.75) 2(-2.35,14.75) 3(2.35,14.25) 4(-2.35,14.25) 5(2.35,13.75) 6(-2.35,13.75) 7(2.35,13.25) 8(-2.35,13.25) 9(2.35,12.75) 10(-2.35,12.75) 11(2.35,12.25) 12(-2.35,12.25) 13(2.35,11.75) 14(-2.35,11.75) 15(2.35,11.25) 16(-2.35,11.25) 17(2.35,10.75) 18(-2.35,10.75) 19(2.35,10.25) 20(-2.35,10.25) 21(2.35,9.75) 22(-2.35,9.75) 23(2.35,9.25) 24(-2.35,9.25) 25(2.35,8.75) 26(-2.35,8.75) 27(2.35,8.25) 28(-2.35,8.25) 29(2.35,7.75) 30(-2.35,7.75) 31(2.35,7.25) 32(-2.35,7.25) 33(2.35,6.75) 34(-2.35,6.75) 35(2.35,6.25) 36(-2.35,6.25) 37(2.35,5.75) 38(-2.35,5.75) 39(2.35,5.25) 40(-2.35,5.25) 41(2.35,4.75) 42(-2.35,4.75) 43(2.35,4.25) 44(-2.35,4.25) 45(2.35,3.75) 46(-2.35,3.75) 47(2.35,3.25) 48(-2.35,3.25) 49(2.35,2.75) 50(-2.35,2.75) 51(2.35,2.25) 52(-2.35,2.25) 53(2.35,1.75) 54(-2.35,1.75) 55(2.35,1.25) 56(-2.35,1.25) 57(2.35,0.75) 58(-2.35,0.75) 59(2.35,0.25) 60(-2.35,0.25) 61(2.35,-0.25) 62(-2.35,-0.25) 63(2.35,-0.75) 64(-2.35,-0.75) 65(2.35,-1.25) 66(-2.35,-1.25) 67(2.35,-1.75) 68(-2.35,-1.75) 69(2.35,-2.25) 70(-2.35,-2.25) 71(2.35,-2.75) 72(-2.35,-2.75) 73(2.35,-3.25) 74(-2.35,-3.25) 75(2.35,-3.75) 76(-2.35,-3.75) 77(2.35,-4.25) 78(-2.35,-4.25) 79(2.35,-4.75) 80(-2.35,-4.75) 81(2.35,-5.25) 82(-2.35,-5.25) 83(2.35,-5.75) 84(-2.35,-5.75) 85(2.35,-6.25) 86(-2.35,-6.25) 87(2.35,-6.75) 88(-2.35,-6.75) 89(2.35,-7.25) 90(-2.35,-7.25) 91(2.35,-7.75) 92(-2.35,-7.75) 93(2.35,-8.25) 94(-2.35,-8.25) 95(2.35,-8.75) 96(-2.35,-8.75) 97(2.35,-9.25) 98(-2.35,-9.25) 99(2.35,-9.75) 100(-2.35,-9.75) 101(2.35,-10.25) 102(-2.35,-10.25) 103(2.35,-10.75) 104(-2.35,-10.75) 105(2.35,-11.25) 106(-2.35,-11.25) 107(2.35,-11.75) 108(-2.35,-11.75) 109(2.35,-12.25) 110(-2.35,-12.25) 111(2.35,-12.75) 112(-2.35,-12.75) 113(2.35,-13.25) 114(-2.35,-13.25) 115(2.35,-13.75) 116(-2.35,-13.75) 117(2.35,-14.25) 118(-2.35,-14.25) 119(2.35,-14.75) 120(-2.35,-14.75)
  rect 2.1x1.6 smd mask+0.051: 121(0,-17.15) 122(0,17.15)
  silkscreen extent -4.33,-17.75 4.25,17.75, body extent -2.9,-17.75 2.9,17.75, height 3.3
"Littlefuse, 0154010.DR" [mm] "Fuse, Fuse with Holder Assembly, Body 9.73mm x 5.03mm, Height 3.81mm"
  rect 4.24x3.81 smd mask+0.051: 1(-3.185,0) 2(3.185,0)
  silkscreen extent -5.74,-2.51 5.74,2.51, body extent -4.86,-2.51 4.86,2.51, height 3.81
"Maglayers, MCM-9070FH0" [mm] "Filter, 4-Leads, Body 9.0mmx7.0mm, Height 4.8mm"
  rect 3x1.75 smd: 1(-4,1.625) 2(-4,-1.625) 3(4,-1.625) 4(4,1.625)
  silkscreen extent -4.45,-3.45 4.55,3.55, body extent -4.75,-3.5 4.75,3.5, height 4.8
"Molex, 22112032" [mil] "Wire Header, DIP, 1x3, Pitch 2.54mm"
  round 70 hole 40.16: 1(0,0) 2(100,0) 3(200,0)
  silkscreen extent -47,-126 247,122, body extent -47,-126 247,124, height 420
"Nexperia, PCMF1USB3S"#1 [mm] "Filter, WLCSP5, Body 1.17mmx0.77mm, Height 0.6mm"
  round 0.26 smd mask+0.051: A1(-0.2,0.4) A2(0.2,0.4) B1(0,0) C1(-0.2,-0.4) C2(0.2,-0.4)
  silkscreen extent -0.39,-0.59 0.39,0.59, body extent -0.38,-0.58 0.39,0.59, height 0.6
"Nexperia, PCMF1USB3S"#2 [mm] "Filter, WLCSP5, Body 1.17mmx0.77mm, Height 0.6mm"
  round 0.26 smd mask+0.051: A1(-0.2,0.4) A2(0.2,0.4) C1(-0.2,-0.4) C2(0.2,-0.4)
  round 0.26 smd mask+0: B1(0,0)
  silkscreen extent -0.39,-0.59 0.39,0.59, body extent -0.38,-0.58 0.39,0.59, height 0.6
"Omron, XF2M-2215-1A" [mm] "Flex Connector, FFC, FPC, 22 pin, 0.50mm Pitch, Dual Contact, Right Angle"
  rect 0.25x1.1 smd mask+0.05: 1(-5.25,1) 2(-4.75,1) 3(-4.25,1) 4(-3.75,1) 5(-3.25,1) 6(-2.75,1) 7(-2.25,1) 8(-1.75,1) 9(-1.25,1) 10(-0.75,1) 11(-0.25,1) 12(0.25,1) 13(0.75,1) 14(1.25,1) 15(1.75,1) 16(2.25,1) 17(2.75,1) 18(3.25,1) 19(3.75,1) 20(4.25,1) 21(4.75,1) 22(5.25,1)
  rect 1.7x1.5 smd mask+0.051: 23(-6.9,-2.9) 24(6.9,-2.9)
  silkscreen extent -7.99,-3.9 7.99,2.05, body extent -7.55,-3.85 7.55,2.05, height 2
"Omron, XF2M-4015-1A" [mm] "Flex Connector, FFC, FPC, 40 pin, 0.50mm Pitch, Dual Contact, SMT, Right Angle"
  rect 0.25x1.1 smd mask+0.05: 1(-9.75,3.9) 2(-9.25,3.9) 3(-8.75,3.9) 4(-8.25,3.9) 5(-7.75,3.9) 6(-7.25,3.9) 7(-6.75,3.9) 8(-6.25,3.9) 9(-5.75,3.9) 10(-5.25,3.9) 11(-4.75,3.9) 12(-4.25,3.9) 13(-3.75,3.9) 14(-3.25,3.9) 15(-2.75,3.9) 16(-2.25,3.9) 17(-1.75,3.9) 18(-1.25,3.9) 19(-0.75,3.9) 20(-0.25,3.9) 21(0.25,3.9) 22(0.75,3.9) 23(1.25,3.9) 24(1.75,3.9) 25(2.25,3.9) 26(2.75,3.9) 27(3.25,3.9) 28(3.75,3.9) 29(4.25,3.9) 30(4.75,3.9) 31(5.25,3.9) 32(5.75,3.9) 33(6.25,3.9) 34(6.75,3.9) 35(7.25,3.9) 36(7.75,3.9) 37(8.25,3.9) 38(8.75,3.9) 39(9.25,3.9) 40(9.75,3.9)
  rect 1.7x1.5 smd mask+0.051: 41(-11.4,0) 42(11.4,0)
  silkscreen extent -12.05,-0.95 12.07,4.95, body extent -12.05,-0.95 12.05,4.95, height 2
"Omron, XF2M-4515-1A" [mm] "Flex Connector, FFC, FPC, 45 pin, 0.50mm Pitch, Dual Contact, SMT, Right Angle"
  rect 0.25x1.1 smd mask+0.05: 1(-11,1.95) 2(-10.5,1.95) 3(-10,1.95) 4(-9.5,1.95) 5(-9,1.95) 6(-8.5,1.95) 7(-8,1.95) 8(-7.5,1.95) 9(-7,1.95) 10(-6.5,1.95) 11(-6,1.95) 12(-5.5,1.95) 13(-5,1.95) 14(-4.5,1.95) 15(-4,1.95) 16(-3.5,1.95) 17(-3,1.95) 18(-2.5,1.95) 19(-2,1.95) 20(-1.5,1.95) 21(-1,1.95) 22(-0.5,1.95) 23(0,1.95) 24(0.5,1.95) 25(1,1.95) 26(1.5,1.95) 27(2,1.95) 28(2.5,1.95) 29(3,1.95) 30(3.5,1.95) 31(4,1.95) 32(4.5,1.95) 33(5,1.95) 34(5.5,1.95) 35(6,1.95) 36(6.5,1.95) 37(7,1.95) 38(7.5,1.95) 39(8,1.95) 40(8.5,1.95) 41(9,1.95) 42(9.5,1.95) 43(10,1.95) 44(10.5,1.95) 45(11,1.95)
  rect 1.7x1.5 smd mask+0.051: 46(-12.65,-1.95) 47(12.65,-1.95)
  silkscreen extent -13.3,-2.9 13.3,3, body extent -13.3,-2.9 13.3,3, height 2
"Oscillator, 4 pin, 1.6mm x 2.0mm" [mm] "Oscillator, 4 pin, Body 1.6mm x 2.0mm, Height 0.85mm"
  rect 0.85x0.75 smd mask+0.051: 1(-0.68,-0.53) 2(0.68,-0.53) 3(0.68,0.53) 4(-0.68,0.53)
  silkscreen extent -1.33,-1.13 1.33,1.12, body extent -1.02,-0.82 1.02,0.83, height 0.85
"Oscillator, 4 pin, 3.2mm x 2.5mm" [mm] "Oscillator, 4 pin, Body 3.2mm x 2.5mm, Height 1.0mm"
  rect 1.4x1.1 smd: 1(-1.1,-0.8) 2(1.1,-0.8) 3(1.1,0.8) 4(-1.1,0.8)
  silkscreen extent -2.02,-1.57 2.03,1.58, body extent -1.6,-1.24 1.6,1.24, height 0.99
"PEM Standoff, M2.0, D5.5," [mm] "PEM Standoff, M2.0, D5.5"
  round 5.5 hole 3.7: 1(0,0)
  body extent -2.75,-2.75 2.75,2.75, height 2.48
"PEM Standoff, M2.0, D5.5, H4.0" [mm] "PEM Standoff, M2.0, D5.5, H4.0"
  round 5.5 hole 2.8 unplated: 1(0,0)
  body extent -2,-2 2,2, height 4
"QFN16, 3.5x3.5, Pitch 0.5mm, Height 1.0mm" [mm] "QFN, 16 pin, 3.5mm x 3.5mm, Pitch 0.5mm, Height 1.0mm, EP 2.14mm x 2.14mm"
  rect 0.85x0.85 on Top Paste mask+0.051: 0(-0.575,-0.575) 0(-0.575,0.575) 0(0.575,-0.575) 0(0.575,0.575)
  rect 0.8x0.28 smd mask+0.051: 1(-1.75,0.75) 2(-1.75,0.25) 3(-1.75,-0.25) 4(-1.75,-0.75) 9(1.75,-0.75) 10(1.75,-0.25) 11(1.75,0.25) 12(1.75,0.75)
  rect 0.28x0.8 smd mask+0.051: 5(-0.75,-1.75) 6(-0.25,-1.75) 7(0.25,-1.75) 8(0.75,-1.75) 13(0.75,1.75) 14(0.25,1.75) 15(-0.25,1.75) 16(-0.75,1.75)
  rect 2.14x2.14 smd paste-100 mask+0.051: 17(0,0)
  silkscreen extent -1.75,-1.75 1.75,1.75, body extent -1.8,-1.8 1.8,1.8, height 1
"QFN24, 4x4, Pitch 0.5mm, Height 0.8mm" [mil] "QFN, 24 pin, 4mm x 4mm, Pitch 0.5mm, Height 0.8mm, EP 2.2mm x 2.2mm"
  oval 32x11 smd mask+2: 1(-77.01,49.21) 2(-77.01,29.53) 3(-77.01,9.84) 4(-77.01,-9.84) 5(-77.01,-29.53) 6(-77.01,-49.21) 13(77.01,-49.21) 14(77.01,-29.53) 15(77.01,-9.84) 16(77.01,9.84) 17(77.01,29.53) 18(77.01,49.21)
  oval 11x32 smd mask+2: 7(-49.21,-77.01) 8(-29.53,-77.01) 9(-9.84,-77.01) 10(9.84,-77.01) 11(29.53,-77.01) 12(49.21,-77.01) 19(49.21,77.01) 20(29.53,77.01) 21(9.84,77.01) 22(-9.84,77.01) 23(-29.53,77.01) 24(-49.21,77.01)
  rect 88x88 smd paste-99999 mask+2: 25(0,0)
  silkscreen extent -88,-88 88,88, body extent -81,-81 81,81, height 31
"QFN32, 5x5, Pitch 0.5mm, Height 0.9mm" [mm] "QFN, 32 pin, 5mm x 5mm, Pitch 0.5mm, Height 0.9mm"
  rrect0% 0.3x0.3 smd mask+0: 1(-2.1,1.75) 8(-2.1,-1.75) 9(-1.75,-2.1) 16(1.75,-2.1) 17(2.1,-1.75) 24(2.1,1.75) 25(1.75,2.1) 32(-1.75,2.1)
  rect 0.5x0.3 smd mask+0.051: 2(-2.1,1.25) 3(-2.1,0.75) 4(-2.1,0.25) 5(-2.1,-0.25) 6(-2.1,-0.75) 7(-2.1,-1.25) 18(2.1,-1.25) 19(2.1,-0.75) 20(2.1,-0.25) 21(2.1,0.25) 22(2.1,0.75) 23(2.1,1.25)
  rect 0.3x0.5 smd mask+0.051: 10(-1.25,-2.1) 11(-0.75,-2.1) 12(-0.25,-2.1) 13(0.25,-2.1) 14(0.75,-2.1) 15(1.25,-2.1) 26(1.25,2.1) 27(0.75,2.1) 28(0.25,2.1) 29(-0.25,2.1) 30(-0.75,2.1) 31(-1.25,2.1)
  rect 3.2x3.2 smd mask+0.051: 33(0,0)
  Top Layer region: -2.35,-1.9 -2.05,-1.9 -1.85,-1.7 -1.85,-1.6 -2.35,-1.6 -2.35,-1.9
  Top Layer region: -1.9,2.35 -1.9,2.05 -1.7,1.85 -1.6,1.85 -1.6,2.35 -1.9,2.35
  Top Layer region: -1.9,-2.35 -1.9,-2.05 -1.7,-1.85 -1.6,-1.85 -1.6,-2.35 -1.9,-2.35
  Top Layer region: -2.35,1.9 -2.05,1.9 -1.85,1.7 -1.85,1.6 -2.35,1.6 -2.35,1.9
  Top Layer region: 1.9,-2.35 1.9,-2.05 1.7,-1.85 1.6,-1.85 1.6,-2.35 1.9,-2.35
  Top Layer region: 2.35,-1.9 2.05,-1.9 1.85,-1.7 1.85,-1.6 2.35,-1.6 2.35,-1.9
  Top Layer region: 2.35,1.9 2.05,1.9 1.85,1.7 1.85,1.6 2.35,1.6 2.35,1.9
  Top Layer region: 1.9,2.35 1.9,2.05 1.7,1.85 1.6,1.85 1.6,2.35 1.9,2.35
  silkscreen extent -2.5,-2.5 2.5,2.5, body extent -2.55,-2.55 2.55,2.55, height 0.9
"QFN32, 5x5, Pitch 0.5mm, Height 1mm" [mm] "QFN, 32 pin, 5mm x 5mm, Pitch 0.5mm, Height 1mm"
  rect 0.7x0.28 smd mask+0.051: 1(-2.4,1.751)
  rect 0.7x0.27 smd mask+0.051: 2(-2.4,1.251) 3(-2.4,0.751) 4(-2.4,0.25) 5(-2.4,-0.25) 6(-2.4,-0.751) 7(-2.4,-1.251) 8(-2.4,-1.751) 17(2.4,-1.751) 18(2.4,-1.251) 19(2.4,-0.751) 20(2.4,-0.25) 21(2.4,0.25) 22(2.4,0.751) 23(2.4,1.251) 24(2.4,1.751)
  rect 0.27x0.7 smd mask+0.051: 9(-1.751,-2.4) 10(-1.251,-2.4) 11(-0.751,-2.4) 12(-0.25,-2.4) 13(0.25,-2.4) 14(0.751,-2.4) 15(1.251,-2.4) 16(1.751,-2.4) 25(1.751,2.4) 26(1.251,2.4) 27(0.751,2.4) 28(0.25,2.4) 29(-0.25,2.4) 30(-0.751,2.4) 31(-1.251,2.4) 32(-1.751,2.4)
  rect 3.607x3.607 smd paste-100 mask+0.051: 33(0,0)
  silkscreen extent -2.68,-2.68 2.68,2.68, body extent -2.55,-2.55 2.55,2.55, height 1
"QFN48, 7x7, Pitch 0.5mm, Height 1.0mm" [mm] "QFN, 48Leads, 7mm x 7mm, Pitch 0.5mm, Height 1.0mm, EP 4.1mm x 4.1mm"
  rect 0.6x0.24 smd mask+0.051: 1(-3.4,2.75) 2(-3.4,2.25) 3(-3.4,1.75) 4(-3.4,1.25) 5(-3.4,0.75) 6(-3.4,0.25) 7(-3.4,-0.25) 8(-3.4,-0.75) 9(-3.4,-1.25) 10(-3.4,-1.75) 11(-3.4,-2.25) 12(-3.4,-2.75) 25(3.4,-2.75) 26(3.4,-2.25) 27(3.4,-1.75) 28(3.4,-1.25) 29(3.4,-0.75) 30(3.4,-0.25) 31(3.4,0.25) 32(3.4,0.75) 33(3.4,1.25) 34(3.4,1.75) 35(3.4,2.25) 36(3.4,2.75)
  rect 0.24x0.6 smd mask+0.051: 13(-2.75,-3.4) 14(-2.25,-3.4) 15(-1.75,-3.4) 16(-1.25,-3.4) 17(-0.75,-3.4) 18(-0.25,-3.4) 19(0.25,-3.4) 20(0.75,-3.4) 21(1.25,-3.4) 22(1.75,-3.4) 23(2.25,-3.4) 24(2.75,-3.4) 37(2.75,3.4) 38(2.25,3.4) 39(1.75,3.4) 40(1.25,3.4) 41(0.75,3.4) 42(0.25,3.4) 43(-0.25,3.4) 44(-0.75,3.4) 45(-1.25,3.4) 46(-1.75,3.4) 47(-2.25,3.4) 48(-2.75,3.4)
  rect 4.1x4.1 smd paste-2.575 mask-100: 49(0,0)
  silkscreen extent -3.72,-3.72 3.73,3.73, body extent -3.55,-3.55 3.55,3.55, height 1
"RES, 1206, Height 0.70mm" [mm] "Resistor, 1206, Height 0.70mm"
  rect 1x1.6 smd: 1(-1.5,0) 2(1.5,0)
  silkscreen extent -1.5,-1.03 1.5,1.02, body extent -1.52,-0.76 1.52,0.76, height 0.7
"RES, R0201, Height 0.23mm" [mm] "Resister, R0201, Height 0.23mm"
  rect 0.352x0.402 smd paste-0.051 mask-0.051: 1(-0.25,0) 2(0.25,0)
  silkscreen extent -0.5,-0.28 0.5,0.28, body extent -0.3,-0.15 0.3,0.15, height 0.23
"RES, R0402, RF" [mm] "Resister, R0402, Height 0.35mm"
  rect 0.452x0.602 smd paste-0.051 mask-0.051: 1(-0.375,0) 2(0.375,0)
  silkscreen extent -0.67,-0.37 0.67,0.37, body extent -0.5,-0.25 0.5,0.25, height 0.35
"RES, R0603, RF" [mil] "Resister, R0603, Height 0.55mm"
  rect 28x36 smd paste-2 mask-2: 1(-26,0) 2(26,0)
  silkscreen extent -43,-21 43,21, body extent -31,-16 32,16, height 28
"RES, R2512, RCS" [mm] "RES, R2512, Height 0.65mm, Current Sense Resistor"
  rect 1.7x0.5 smd mask+0.051: 1(-2.788,0) 2(2.788,0)
  Top Layer region: 1.934,-0.497 1.934,-1.747 3.634,-1.747 3.634,-0.497
  Top Layer region: 3.637,0.499 3.637,1.749 1.937,1.749 1.937,0.499
  Top Layer region: -1.937,0.5 -1.937,1.75 -3.637,1.75 -3.637,0.5
  Top Layer region: -3.637,-0.508 -3.637,-1.758 -1.937,-1.758 -1.937,-0.508
  silkscreen extent -3.85,-2 3.85,2, body extent -3.25,-1.7 3.25,1.7, height 0.75
SC70-6 [mil] "SC70, 6 pin, 2.0x2.4mm , Height 1.1mm"
  rect 16x24 smd: 1(-25.59,-37.5) 2(0,-37.5) 3(25.59,-37.5) 4(25.59,37.5) 5(0,37.5) 6(-25.59,37.5)
  silkscreen extent -44,-31 44,31, body extent -44,-41 41,41, height 37
"SC-70, 3 Leads, 2.1mm x 2.0mm, Height 1.1mm, SMD" [mm] "SC-70, 3 Leads, 2.1mm x 2.0mm, Height 1.1mm"
  rect 1.05x0.5 smd paste-0.051 mask-0.051: 1(-1.1,0.65) 2(-1.1,-0.65) 3(1.1,0)
  silkscreen extent -1.69,-1 1.69,1, body extent -1.05,-1 1.05,1, height 1.09
"Screw Hole, Hole 1.524mm, Dia 1.524mm" [mil] "Screw Hole, Hole 1.524mm, Dia 1.524mm"
  round 60 hole 60 unplated: 1(0,0)
"Screw Hole, Hole 3.2mm, Dia 6mm" [mm] "Screw Hole, Hole 3.2mm, Dia 6mm"
  round 6 hole 3.2 unplated: 1(0,0)
  body extent -3,-3 3,3, height 0.01
SIP1x5_100P [mil] "Header, 5-Leads, Pitch 2.54mm"
  rect 70x70 hole 42: 1(0,0)
  round 70 hole 42: 2(100,0) 3(200,0) 4(300,0) 5(400,0)
  silkscreen extent -49,-51 450,51, body extent -50,-50 450,50, height 335
SOD323 [mil] "SOD323, Body L 2.70mm x W 1.35mm x H 1.1mm"
  rect 35x18 smd: 1(-47.24,0) 2(47.24,0)
  silkscreen extent -75,-31 40,31, body extent -51,-27 51,27, height 43
SOD523#1 [mm] "SOD523, Body 1.2mm x 0.8mm, Height 0.6mm"
  rect 0.6x0.5 smd: 1(-0.8,0) 2(0.8,0)
  silkscreen extent -1.37,-0.53 0.71,0.53, body extent -0.85,-0.45 0.85,0.45, height 0.7
SOD523#2 [mm] "SOD523, Body 1.2mm x 0.8mm, Height 0.6mm"
  rect 0.6x0.5 smd mask+0.051: 1(-0.8,0) 2(0.8,0)
  silkscreen extent -1.37,-0.53 0.71,0.53, body extent -0.85,-0.45 0.85,0.45, height 0.7
SOIC-8 [mm] "SOIC, 8-Leads, Body 6x4.9mm, Height 1.75mm, Pitch 1.27mm"
  rect 1.55x0.6 smd mask+0.051: 1(-2.7,1.905) 2(-2.7,0.635) 3(-2.7,-0.635) 4(-2.7,-1.905) 5(2.7,-1.905) 6(2.7,-0.635) 7(2.7,0.635) 8(2.7,1.905)
  silkscreen extent -1.95,-2.45 1.95,2.45, body extent -3,-2.45 3,2.45, height 1.75
"Solder Bridge Closed" [mil] "Solderbridge Closed"
  round 1 smd paste-99999 mask+1: 1(-17.72,0) 2(17.72,0)
  Top Layer region: -11.77,19.68 -15.58,18.93 -19.17,17.44 -22.39,15.29 -25.13,12.55 -27.29,9.32 -28.77,5.74 -29.53,1.94 -29.53,-1.94 -28.77,-5.74 -27.29,-9.32 -25.13,-12.55 -22.39,-15.29 -19.17,-17.44 -15.58,-18.93 -11.77,-19.69 -5.91,-19.69 -5.91,19.68
  Top Layer region: 11.77,-19.69 15.58,-18.93 19.17,-17.44 22.39,-15.29 25.13,-12.55 27.29,-9.32 28.77,-5.74 29.53,-1.94 29.53,1.94 28.77,5.74 27.29,9.32 25.13,12.55 22.39,15.29 19.17,17.44 15.58,18.93 11.77,19.68 5.91,19.68 5.91,-19.69
  Top Layer lines w9.84: -6,0 6,0
  body extent -30,-20 30,20, height 2
"Solder Bridge Open" [mil] "WTS Solderbridge Open"
  round 1 smd paste-99999 mask+1: 1(-17.72,0) 2(17.72,0)
  Top Layer region: 11.77,-19.69 15.58,-18.93 19.17,-17.44 22.39,-15.29 25.13,-12.55 27.29,-9.32 28.77,-5.74 29.53,-1.94 29.53,1.94 28.77,5.74 27.29,9.32 25.13,12.55 22.39,15.29 19.17,17.44 15.58,18.93 11.77,19.69 5.91,19.69 5.91,-19.69
  Top Layer region: -11.77,19.69 -15.58,18.93 -19.17,17.44 -22.39,15.29 -25.13,12.55 -27.29,9.32 -28.77,5.74 -29.53,1.94 -29.53,-1.94 -28.77,-5.74 -27.29,-9.32 -25.13,-12.55 -22.39,-15.29 -19.17,-17.44 -15.58,-18.93 -11.77,-19.69 -5.91,-19.69 -5.91,19.69
  body extent -30,-20 30,20, height 2
SON8 [mm] "SON, 8-Lead, Body 3.15mm x 3mm, Pitch 0.65mm, Height 0.9mm"
  rect 0.6x0.3 smd mask+0.051: 1(-1.55,0.975) 2(-1.55,0.325) 3(-1.55,-0.325) 4(-1.55,-0.975)
  rect 0.635x0.3 smd mask+0.051: 5(1.524,-0.975) 6(1.524,-0.325) 7(1.524,0.325) 8(1.524,0.975)
  Top Layer region: -0.559,-1.225 1.216,-1.225 1.216,1.225 -0.559,1.225
  silkscreen extent -1.97,-1.58 1.97,1.58, body extent -1.65,-1.58 1.65,1.58, height 0.9
"SON14, 4.5mm x 3mm x 1mm, SMD" [mm] "SON14, 14 pin, 4.5mm x 3mm, Height 1mm, Pitch 0.65mm"
  rect 0.7x0.4 smd paste-0.051 mask-0.051: 1(-1.45,1.95) 2(-1.45,1.3) 3(-1.45,0.65) 4(-1.45,0) 5(-1.45,-0.65) 6(-1.45,-1.3) 7(-1.45,-1.95) 8(1.45,-1.95) 9(1.45,-1.3) 10(1.45,-0.65) 11(1.45,0) 12(1.45,0.65) 13(1.45,1.3) 14(1.45,1.95)
  rect 1.7x4.3 smd paste-2539.97 mask-0.051: 15(0,0)
  silkscreen extent -1.5,-2.25 1.5,2.25, body extent -1.55,-2.25 1.55,2.25, height 1
"SOT8, 2.1x1.6mm, Height 0.6mm" [mm] "SOT8, 8-Leads, Body 2.1x1.6mm, Pitch 0.5mm"
  rect 0.67x0.3 smd mask+0.081: 1(-0.74,0.75) 2(-0.74,0.25) 3(-0.74,-0.25) 4(-0.74,-0.75) 5(0.74,-0.75) 6(0.74,-0.25) 7(0.74,0.25) 8(0.74,0.75)
  silkscreen extent -0.8,-1.05 0.8,1.05, body extent -0.8,-1.05 0.8,1.05, height 0.61
SOT23 [mil] "SOT23, 3-Leads, Body 3.10x2.95mm, Height 1.30mm"
  rect 30x36 smd: 1(-35,-39) 2(35,-39)
  rect 30x40 smd: 3(0,38)
  silkscreen extent -59,-29 59,29, body extent -59,-49 59,49, height 44
"SOT23_6, Height 1.45mm" [mm] "SOT23, 6-Leads, Body 2.9x1.6mm, Height 1.45mm, Pitch 0.95mm"
  rect 1.2x0.6 smd mask+0.051: 1(-1.3,0.95) 2(-1.3,0) 3(-1.3,-0.95) 4(1.3,-0.95) 5(1.3,0) 6(1.3,0.95)
  silkscreen extent -0.8,-1.45 0.8,1.45, body extent -1.4,-1.45 1.4,1.45, height 1.45
"SOT23_8, Height 1.1mm" [mm] "SOT23, 8-Leads, Body 2.8x2.9mm, Height 1.1mm, Pitch 0.65mm"
  rect 1.05x0.45 smd mask+0.051: 1(-1.3,0.975) 2(-1.3,0.325) 3(-1.3,-0.325) 4(-1.3,-0.975) 5(1.3,-0.975) 6(1.3,-0.325) 7(1.3,0.325) 8(1.3,0.975)
  silkscreen extent -0.8,-1.45 0.8,1.45, body extent -1.4,-1.45 1.4,1.45, height 1.1
SOT523 [mm] "SOT523, 3-Leads, Body 1.75x1.70mm, Height 0.9mm"
  rect 0.457x0.635 smd: 1(-0.5,-0.7) 2(0.5,-0.7) 3(0,0.7)
  silkscreen extent -1,-0.5 1,0.63, body extent -0.8,-0.83 0.8,0.8, height 0.81
"Sullins, QPC02SXGN-RC" [mil] "Th, Shorting Jumper, 2.54mm, Black Open Top"
  body extent -98,-47 98,47, height 336
"TC2050-FP, TAG Test Interface, Mounted" [mil] "TC2050-FP, TAG Test Interface, Mounted"
  round 93.5 hole 93.5 unplated mask+4: 0(-150,-100) 0(-150,100) 0(75,-100) 0(75,100)
  round 31 smd paste-99999 mask+2: 1(-100,-25) 2(-50,-25) 3(0,-25) 4(50,-25) 5(100,-25) 6(100,25) 7(50,25) 8(0,25) 9(-50,25) 10(-100,25)
  round 39.02 hole 39 unplated mask+4: 11(-150,0) 12(150,40) 13(150,-40)
  silkscreen extent -189,-83 193,87
"Test Point, SMT 1mm Round" [mm] "Test Point, SMT 1mm Round"
  round 1 smd paste-1.27 mask+0.051: 1(0,0)
  silkscreen extent -0.63,-0.64 0.63,0.63
"Test Point, SMT 20mil Round" [mil] "Test Point, SMT 20mil Round"
  round 20 smd paste-50 mask+2: 1(0,0)
  silkscreen extent -15,-15 15,15
"Test Point, TH 1mm Round with test ring, Green" [mm] "Test Point, TH 1mm Round with test ring, Green"
  round 1.3 / inner round 1.3 / far side round 1.8 hole 1 mask+0.025: 1(0,0)
  silkscreen extent -1.6,-1.6 1.6,1.6, body extent -1.6,-1.6 1.67,1.6, height 5.2
"Test Point, TH 1mm Round with test ring, Red" [mm] "Test Point, TH 1mm Round with test ring, Red"
  round 1.3 / inner round 1.3 / far side round 1.8 hole 1 mask+0.025: 1(0,0)
  silkscreen extent -1.6,-1.6 1.6,1.6, body extent -1.6,-1.6 1.67,1.6, height 5.2
"TI, RUT12" [mm] "QFN, 12-Leads, Body 1.7x2mm, Pitch 0.4mm, TI Recommended"
  rect 0.6x0.2 smd paste-0.2 mask+0.05: 1(-0.65,0.8) 2(-0.65,0.4) 3(-0.65,0) 4(-0.65,-0.4) 5(-0.65,-0.8) 7(0.65,-0.8) 8(0.65,-0.4) 9(0.65,0) 10(0.65,0.4) 11(0.65,0.8)
  rect 0.2x0.6 smd paste-0.2 mask+0.05: 6(0,-0.8) 12(0,0.8)
  Top Layer region: -0.5,1.1 -0.35,1.1 -0.35,0.9 -0.5,0.9
  silkscreen extent -0.9,-1.2 0.9,1.2, body extent -0.9,-1.05 0.9,1.05, height 0.55
"TI, SN74LVC1G08DPWR" [mm] "4X2SON"
  rect 0.1x0.1 smd mask+0: 1(-0.346,0.261) 2(-0.346,-0.261) 4(0.346,-0.261) 5(0.346,0.261)
  rrect50% 0.24x0.24 smd rot 135: 3(0,0)
  Top Layer region: 0.444,-0.13 0.444,-0.35 0.18,-0.35 0.18,-0.29 0.34,-0.13
  Top Layer region: -0.444,-0.13 -0.444,-0.35 -0.18,-0.35 -0.18,-0.29 -0.34,-0.13
  Top Layer region: -0.444,0.13 -0.444,0.35 -0.18,0.35 -0.18,0.29 -0.34,0.13
  Top Layer region: 0.444,0.13 0.444,0.35 0.18,0.35 0.18,0.29 0.34,0.13
  body extent -0.4,-0.4 0.4,0.4, height 0.4
"TI, SOT23-5 (DDC0005A)" [mm] "SOT23, 5-Leads, Body 3.05x1.75mm, Pitch 0.95mm, IPC High Density"
  rrect18% 0.8x0.55 smd: 1(-1.275,0.95) 2(-1.275,0) 3(-1.275,-0.95) 4(1.275,-0.95) 5(1.275,0.95)
  silkscreen extent -1.4,-1.55 0.5,1.9, body extent -1.4,-1.45 1.4,1.45, height 1.45
"TOUKE, TK18-001-A" [mm] "DC Power jack"
  rect 1.154x3.254 / inner rect 1.154x3.254 / far side rect 1.713x3.813 hole 0.9 slot 2.85 at 90 deg: 1(3.1,2.325)
  oval 1.154x3.254 / inner oval 1.154x3.254 / far side oval 1.713x3.813 hole 0.9 slot 2.85 at 90 deg: 2(-3.1,2.325)
  oval 3.254x1.154 / inner oval 3.254x1.154 / far side oval 3.813x1.713 hole 0.9 slot 2.85 at 0 deg: 3(0.1,-2.325)
  silkscreen extent -10.65,-2.17 3.8,6.83, body extent -10.65,-2.36 3.75,7.04, height 11
"TSSOP8, 4.9x3, Pitch 0.65mm, Height 1.1mm" [mil] "TSSOP8, 8-Leads, Body 4.9mm x 3mm, Pitch 0.65mm, Height 1.1mm"
  rect 57x18 smd mask+2: 1(-84.65,38.39) 2(-84.65,12.8) 3(-84.65,-12.8) 4(-84.65,-38.39) 5(84.65,-38.39) 6(84.65,-12.8) 7(84.65,12.8) 8(84.65,38.39)
  silkscreen extent -72,-68 68,68, body extent -96,-59 96,59, height 43
"TSSOP16, 16-Leads, Body 5.0mm x 4.4mm, Height 1.2mm, Pitch 0.65mm" [mil] "TSSOP16, 16-Leads, Body 5.0mm x 4.4mm, Height 1.2mm, Pitch 0.65mm"
  oval 70x15.75 smd: 1(-102.65,89.22) 2(-102.65,63.63) 3(-102.65,38.04) 4(-102.65,12.45) 5(-102.65,-13.14) 6(-102.65,-38.73) 7(-102.65,-64.32) 8(-102.65,-89.91) 9(102.35,-89.91) 10(102.35,-64.32) 11(102.35,-38.73) 12(102.35,-13.14) 13(102.35,12.45) 14(102.35,38.04) 15(102.35,63.63) 16(102.35,89.22)
  silkscreen extent -86,-107 86,106, body extent -126,-99 126,98, height 43
"UQFN16, 2.6x1.8, Pitch 0.4mm, Height 0.5mm" [mm] "UQFN, 16 pin, 2.6mm x 1.8mm, Pitch 0.4mm, Height 0.5mm"
  rect 0.8x0.24 smd mask+0.051: 1(-0.7,0.6)
  rect 0.6x0.24 smd mask+0.051: 2(-0.8,0.2) 3(-0.8,-0.2) 4(-0.8,-0.6) 9(0.8,-0.6) 10(0.8,-0.2) 11(0.8,0.2) 12(0.8,0.6)
  rect 0.24x0.6 smd mask+0.051: 5(-0.6,-1.2) 6(-0.2,-1.2) 7(0.2,-1.2) 8(0.6,-1.2) 13(0.6,1.2) 14(0.2,1.2) 15(-0.2,1.2) 16(-0.6,1.2)
  silkscreen extent -1.01,-1.39 1.01,1.42, body extent -0.95,-1.35 0.95,1.35, height 0.55
VFSOP8_2x2.3 [mm] "VFSOP, 8 pin, 2mm x 2.3mm"
  oval 0.3x0.8 smd: 1(-0.75,-1.55) 2(-0.25,-1.55) 3(0.25,-1.55) 4(0.75,-1.55) 5(0.75,1.55) 6(0.25,1.55) 7(-0.25,1.55) 8(-0.75,1.55)
  silkscreen extent -1.1,-0.85 1.1,0.8, body extent -1,-1.55 1,1.55, height 0.91
"VQFN20, 2.5x4.5, Pitch 0.5mm, Height 1.0mm, SMD" [mm] "VQFN, 20 pin, 2.5mm x 4.5mm, Pitch 0.5mm, Height 1.0mm, EP 1mm x 3mm"
  rect 0.35x0.7 smd paste-0.051 mask-0.051: 1(-0.25,2.15) 10(-0.25,-2.15) 11(0.25,-2.15) 20(0.25,2.15)
  rect 0.7x0.35 smd paste-0.051 mask-0.051: 2(-1.15,1.75) 3(-1.15,1.25) 4(-1.15,0.75) 5(-1.15,0.25) 6(-1.15,-0.25) 7(-1.15,-0.75) 8(-1.15,-1.25) 9(-1.15,-1.75) 12(1.15,-1.75) 13(1.15,-1.25) 14(1.15,-0.75) 15(1.15,-0.25) 16(1.15,0.25) 17(1.15,0.75) 18(1.15,1.25) 19(1.15,1.75)
  rect 1.1x3.1 smd paste-100 mask-0.051: 21(0,0)
  silkscreen extent -1.6,-2.6 1.6,2.6, body extent -1.25,-2.25 1.25,2.25, height 0.96
"VQFN24, 4x4, Pitch 0.5mm, Height 0.9mm" [mm] "QFN, 24 pin, 4mm x 4mm, Pitch 0.5mm, Height 0.9mm, EP 2.6mm x 2.6mm"
  oval 0.85x0.3 smd mask+0.051: 1(-1.95,1.25) 2(-1.95,0.75) 3(-1.95,0.25) 4(-1.95,-0.25) 5(-1.95,-0.75) 6(-1.95,-1.25) 13(1.95,-1.25) 14(1.95,-0.75) 15(1.95,-0.25) 16(1.95,0.25) 17(1.95,0.75) 18(1.95,1.25)
  oval 0.3x0.85 smd mask+0.051: 7(-1.25,-1.95) 8(-0.75,-1.95) 9(-0.25,-1.95) 10(0.25,-1.95) 11(0.75,-1.95) 12(1.25,-1.95) 19(1.25,1.95) 20(0.75,1.95) 21(0.25,1.95) 22(-0.25,1.95) 23(-0.75,1.95) 24(-1.25,1.95)
  rect 2.6x2.6 smd paste-2539.97 mask+0.051: 25(0,0)
  silkscreen extent -2.24,-2.24 2.24,2.24, body extent -2.01,-2.01 2.01,2.01, height 0.92
"VQFN24, 4x4, Pitch 0.5mm, Height 1.0mm, SMD with Anchor Pads" [mm] "VQFN, 24 pins, 4mm x 4mm, Pitch 0.5mm, Height 1.0mm, EP 2.1mm x 2.1mm"
  rect 0.7x0.34 smd paste-0.051 mask-0.051: 1(-1.9,1.25) 2(-1.9,0.75) 3(-1.9,0.25) 4(-1.9,-0.25) 5(-1.9,-0.75) 6(-1.9,-1.25) 13(1.9,-1.25) 14(1.9,-0.75) 15(1.9,-0.25) 16(1.9,0.25) 17(1.9,0.75) 18(1.9,1.25)
  rect 0.34x0.7 smd paste-0.051 mask-0.051: 7(-1.25,-1.9) 8(-0.75,-1.9) 9(-0.25,-1.9) 10(0.25,-1.9) 11(0.75,-1.9) 12(1.25,-1.9) 19(1.25,1.9) 20(0.75,1.9) 21(0.25,1.9) 22(-0.25,1.9) 23(-0.75,1.9) 24(-1.25,1.9)
  rect 2.2x2.2 smd paste-2539.97 mask-0.051: 25(0,0)
  rect 0.35x0.35 smd paste-0.051 mask-0.051: A1(-1.725,1.725) A2(-1.725,-1.725) A3(1.725,-1.725) A4(1.725,1.725)
  silkscreen extent -2.12,-2.12 2.12,2.13, body extent -2,-2.01 2.01,2, height 0.9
